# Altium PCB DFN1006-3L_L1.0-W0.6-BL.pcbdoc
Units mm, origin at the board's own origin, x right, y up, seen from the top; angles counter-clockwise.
Board outline 14.16 x 13.89 mm, 2 copper layers (Top Layer, Bottom Layer), stack 0 mm thick; 1 components, 0 nets, 3 pads, 0 vias.
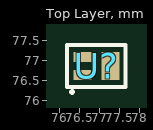
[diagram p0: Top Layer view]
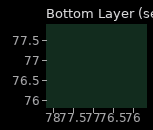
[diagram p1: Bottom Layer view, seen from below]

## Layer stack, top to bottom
Top Layer: signal copper (thickness not stored)
Bottom Layer: signal copper (thickness not stored)

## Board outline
84.01,69.85 69.85,69.85 69.85,83.74 84.01,83.74

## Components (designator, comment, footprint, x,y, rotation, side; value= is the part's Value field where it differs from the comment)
U? "" DFN1006-3L_L1.0-W0.6-BL 76.93,76.87 r0 top

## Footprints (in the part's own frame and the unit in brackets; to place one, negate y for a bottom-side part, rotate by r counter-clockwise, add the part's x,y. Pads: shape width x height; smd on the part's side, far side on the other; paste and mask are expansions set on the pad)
DFN1006-3L_L1.0-W0.6-BL [mm]
  rect 0.45x0.25 smd: 1(-0.35,-0.225) 3(-0.35,0.225)
  rect 0.45x0.7 smd: 2(0.35,0)
  silkscreen extent -0.73,-0.67 0.73,0.52

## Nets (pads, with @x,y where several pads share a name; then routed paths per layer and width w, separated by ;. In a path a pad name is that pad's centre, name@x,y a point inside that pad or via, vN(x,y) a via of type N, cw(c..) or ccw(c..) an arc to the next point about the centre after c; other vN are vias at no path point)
pads on no net: U?.1 U?.2 U?.3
